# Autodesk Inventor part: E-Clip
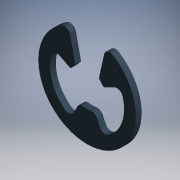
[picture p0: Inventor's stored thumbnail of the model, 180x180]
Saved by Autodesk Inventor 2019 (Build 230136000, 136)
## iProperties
Shininess: 50.0
Compacted: True
Length Units: 11272
Angle Units: 11279
Time Units: 11290
Mass Units: 11286
Length Display Precision: 4
Angle Display Precision: 2
Company: Autodesk
Created: 2000-03
Part Number: E-Clip
Project: Inventor Samples
Document SubType Name: Modeling
Designer: Autodesk, Inc.
Density: 1.13 g/cm^3
Mass: 0.00688314 g
Surface Area: 0.451156 cm^2
Volume: 0.00609128 cm^3
Material: Nylon-6/6
Appearance: Dark Blue Grey
Density: 0.0
Volumn: 0.0
Area: 0.0
PropertySet Name: Model Information
Control State: 0
Master: False
Checked Out: False
Checked Out Date: 2018-05-30
Last Check In Date: 2018-05-30
Author: Autodesk, Inc.
Revision Number: A
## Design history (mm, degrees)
node "Extrusion1" dims "d2" = 0.381, "d3" = 0
  sketch "Sketch2"
    geometry: C1 r 3.175 at (-5.202, -4.223); C2 r 1.191 at (-5.202, -4.223)
    constraints: 2 centre point, 1 coincident
    dimensions: "d0" = 2.38125 diameter of C2; "d1" = 6.35 diameter of C1
node "Extrusion2" dims "d9" = 0.381, "d10" = 0
  sketch "Sketch3"
    geometry: L1 (-0.635, 0.311)-(0.635, 0.311); L2 (0.635, 0.311)-(1.27, 3.175); L3 (1.27, 3.175)-(-1.27, 3.175); L4 (-1.27, 3.175)-(-0.635, 0.311); C1 r 1.191 at (0, 0) reference; C2 r 3.175 at (0, 0) reference
    constraints: 8 end point, 1 horizontal, 1 parallel, 1 tangent
    dimensions: "d4" = 2.54 distance of L2.end L3.end; "d5" = 1.27 distance of L1.start L1.end; "d6" = 1.27 horizontal distance of C1.centre L3.end (= 0.5 x d4); "d7" = 25 deg angle of L2 L4; "d8" = 0.635 horizontal distance of C1.centre L1.start (= 0.5 x d5)
node "Extrusion3" dims "d16" = 0.381, "d17" = 0
  sketch "Sketch4"
    geometry: L1 (-3.986, -1.29)-(-4.434, -3.313) reference; L2 (-5.97, -3.313)-(-6.418, -1.29) reference; L3 (-5.705, -5.302)-(-6.222, -6.41); L4 (-4.699, -5.302)-(-4.182, -6.41); L5 (-6.281, -4.726)-(-6.281, -4.726); L6 (-5.705, -5.302)-(-5.705, -5.302); L7 (-6.258, -3.673)-(-7.342, -3.109); L8 (-4.146, -3.673)-(-3.062, -3.109); A1 r 3.175 centre (-5.202, -4.223) between (-6.418, -1.29) and (-3.986, -1.29) reference; A2 r 2.413 centre (-5.202, -4.223) between (-7.342, -3.109) and (-3.062, -3.109); 2 further points
    constraints: 12 end point, 5 point on circle, 4 point on line, 1 centre point, 1 coincident, 1 parallel, 1 vertical alignment, 10 other
    dimensions: "d11" = 50 deg angle of L4 L3; "d12" = 0.762 radial gap between concentric circles of A1 A2; "d13" = 25 deg dimension on point (-5.202, -4.223) point (-5.202, -7.398) L3.end (= 0.5 x d11); "d14" = 50 deg angle of L2 L7; "d15" = 50 deg angle of L8 L1 (= d14)
node "Fillet1" dims "d18" = 0.381, "d19" = 0.127
workaxis "Work Axis1"
body "Solid1"
